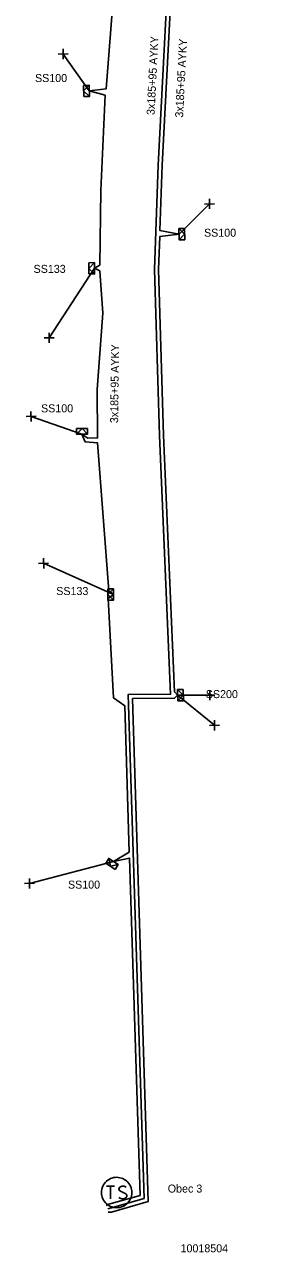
# Model space of a CAD drawing. Extents: x -762894 to -762498, y -1152897 to -1152214.
# Drawn here: x -762774.4 to -762745.3, y -1152511.5 to -1152359 of the extents above; entities that cross this region are included whole.
import ezdxf

# ---------------------------------------------------------------- set-up
doc = ezdxf.new("R2010")
doc.units = 0
for name, color, linetype in [('Vrstva 25', 7, 'Continuous'), ('Vrstva 26', 7, 'Continuous'), ('Vrstva 27', 7, 'Continuous'), ('Vrstva 31', 7, 'Continuous'), ('Vrstva 33', 7, 'Continuous'), ('Vrstva 34', 7, 'Continuous'), ('Vrstva 5', 7, 'Continuous'), ('Vrstva 59', 7, 'Continuous'), ('Vrstva 6', 7, 'Continuous')]:
    doc.layers.add(name, color=color, linetype=linetype)

msp = doc.modelspace()

# ---------------------------------------------------------------- linework, layer by layer
at = {"layer": 'Vrstva 25'}
for points in [[(-762761.027, -1152504.021), (-762761.038, -1152503.824), (-762761.069, -1152503.628), (-762761.12, -1152503.437), (-762761.192, -1152503.252), (-762761.281, -1152503.077), (-762761.389, -1152502.911), (-762761.513, -1152502.757), (-762761.653, -1152502.617), (-762761.807, -1152502.493), (-762761.973, -1152502.385), (-762762.149, -1152502.295), (-762762.333, -1152502.224), (-762762.72, -1152502.142), (-762762.72, -1152502.142), (-762762.917, -1152502.131), (-762763.115, -1152502.142), (-762763.311, -1152502.173), (-762763.501, -1152502.224), (-762763.687, -1152502.295), (-762763.862, -1152502.385), (-762764.028, -1152502.493), (-762764.182, -1152502.617), (-762764.322, -1152502.757), (-762764.446, -1152502.911), (-762764.554, -1152503.077), (-762764.644, -1152503.252), (-762764.715, -1152503.437), (-762764.766, -1152503.628), (-762764.797, -1152503.824), (-762764.808, -1152504.021), (-762764.797, -1152504.219), (-762764.766, -1152504.415), (-762764.715, -1152504.605), (-762764.644, -1152504.79), (-762764.554, -1152504.966), (-762764.446, -1152505.132), (-762764.321, -1152505.286), (-762764.182, -1152505.425), (-762764.028, -1152505.55), (-762763.862, -1152505.658), (-762763.686, -1152505.748), (-762763.501, -1152505.819), (-762763.311, -1152505.87), (-762763.115, -1152505.901), (-762762.917, -1152505.912), (-762762.72, -1152505.901), (-762762.525, -1152505.87), (-762762.333, -1152505.819), (-762762.149, -1152505.748), (-762761.973, -1152505.658), (-762761.807, -1152505.55), (-762761.653, -1152505.425), (-762761.513, -1152505.286), (-762761.389, -1152505.132), (-762761.281, -1152504.966), (-762761.192, -1152504.79), (-762761.12, -1152504.605), (-762761.069, -1152504.415), (-762761.038, -1152504.219), (-762761.027, -1152504.021)], [(-762764.179, -1152503.238), (-762763.171, -1152503.238)], [(-762763.675, -1152503.238), (-762763.675, -1152504.812)], [(-762761.722, -1152503.364), (-762761.974, -1152503.238), (-762762.289, -1152503.238), (-762762.541, -1152503.364), (-762762.667, -1152503.552), (-762762.667, -1152503.616), (-762762.541, -1152503.804), (-762761.785, -1152504.182), (-762761.659, -1152504.34), (-762761.659, -1152504.498), (-762761.785, -1152504.686), (-762762.037, -1152504.812), (-762762.289, -1152504.812), (-762762.415, -1152504.75), (-762762.667, -1152504.624)]]:
    msp.add_lwpolyline(points, dxfattribs=at)
at = {"layer": 'Vrstva 31'}
for points in [[(-762767.033, -1152366.519), (-762766.333, -1152366.507), (-762766.308, -1152367.907), (-762767.008, -1152367.919)], [(-762767.033, -1152366.519), (-762767.008, -1152367.919)], [(-762767.02, -1152367.219), (-762766.333, -1152366.507)], [(-762767.02, -1152367.219), (-762766.308, -1152367.907)], [(-762754.447, -1152385.691), (-762755.147, -1152385.703), (-762755.172, -1152384.303), (-762754.472, -1152384.291)], [(-762754.46, -1152384.991), (-762755.172, -1152384.303)], [(-762754.447, -1152385.691), (-762754.472, -1152384.291)], [(-762754.46, -1152384.991), (-762755.147, -1152385.703)], [(-762766.393, -1152388.549), (-762765.693, -1152388.537), (-762765.668, -1152389.937), (-762766.368, -1152389.949)], [(-762766.393, -1152388.549), (-762766.368, -1152389.949)], [(-762766.38, -1152389.249), (-762765.693, -1152388.537)], [(-762766.38, -1152389.249), (-762765.668, -1152389.937)], [(-762766.527, -1152409.13), (-762767.927, -1152409.13)], [(-762767.227, -1152409.13), (-762767.927, -1152409.83)], [(-762766.527, -1152409.13), (-762766.527, -1152409.83), (-762767.927, -1152409.83), (-762767.927, -1152409.13)], [(-762767.227, -1152409.13), (-762766.527, -1152409.83)], [(-762764.023, -1152429.049), (-762763.323, -1152429.037), (-762763.298, -1152430.437), (-762763.998, -1152430.449)], [(-762764.023, -1152429.049), (-762763.998, -1152430.449)], [(-762764.01, -1152429.749), (-762763.323, -1152429.037)], [(-762764.01, -1152429.749), (-762763.298, -1152430.437)], [(-762754.617, -1152442.941), (-762755.317, -1152442.953), (-762755.342, -1152441.553), (-762754.642, -1152441.541)], [(-762754.63, -1152442.241), (-762755.342, -1152441.553)], [(-762754.63, -1152442.241), (-762755.317, -1152442.953)], [(-762754.617, -1152442.941), (-762754.642, -1152441.541)], [(-762764.281, -1152463.125), (-762763.9, -1152462.538), (-762762.726, -1152463.3), (-762763.107, -1152463.887)], [(-762764.281, -1152463.125), (-762763.107, -1152463.887)], [(-762763.694, -1152463.506), (-762763.9, -1152462.538)], [(-762763.694, -1152463.506), (-762762.726, -1152463.3)]]:
    msp.add_lwpolyline(points, dxfattribs=at)
at = {"layer": 'Vrstva 34'}
for points in [[(-762770.185, -1152362.641), (-762768.935, -1152362.619)], [(-762769.549, -1152363.255), (-762769.571, -1152362.005)], [(-762752.005, -1152381.261), (-762750.755, -1152381.239)], [(-762751.369, -1152381.875), (-762751.391, -1152380.625)], [(-762771.935, -1152397.891), (-762770.685, -1152397.869)], [(-762771.299, -1152398.505), (-762771.321, -1152397.255)], [(-762773.549, -1152408.255), (-762773.571, -1152407.005)], [(-762774.185, -1152407.641), (-762772.935, -1152407.619)], [(-762771.989, -1152426.505), (-762772.011, -1152425.255)], [(-762772.625, -1152425.891), (-762771.375, -1152425.869)], [(-762751.955, -1152442.261), (-762750.705, -1152442.239)], [(-762751.319, -1152442.875), (-762751.341, -1152441.625)], [(-762751.375, -1152446.011), (-762750.125, -1152445.989)], [(-762750.739, -1152446.625), (-762750.761, -1152445.375)], [(-762773.739, -1152466.255), (-762773.761, -1152465.005)], [(-762774.375, -1152465.641), (-762773.125, -1152465.619)]]:
    msp.add_lwpolyline(points, dxfattribs=at)
at = {"layer": 'Vrstva 5'}
for points in [[(-762764.03, -1152506.05), (-762759.5, -1152504.75), (-762761.48, -1152442.16), (-762756.22, -1152442.14), (-762757.58, -1152410), (-762758.2, -1152389.39), (-762757.76, -1152376.42), (-762756.07, -1152343.75), (-762754.03, -1152318), (-762754.3, -1152317.61), (-762753.99, -1152314.18), (-762753.67, -1152314.11), (-762751.63, -1152292.79), (-762750.29, -1152273.43), (-762745.47, -1152272.59), (-762745.28, -1152272.45)], [(-762763.98, -1152506.47), (-762763.55, -1152506.48), (-762758.99, -1152505.12), (-762760.93, -1152442.68), (-762755.72, -1152442.63), (-762755.33, -1152442.25), (-762755.74, -1152441.83), (-762757.08, -1152409.98), (-762757.7, -1152389.39), (-762757.56, -1152385.31), (-762755.16, -1152385), (-762757.54, -1152384.55), (-762757.26, -1152376.45), (-762755.57, -1152343.78)], [(-762762.63, -1152346.79), (-762764.22, -1152366.95), (-762766.32, -1152367.21), (-762764.36, -1152367.75), (-762764.89, -1152379.56), (-762765.02, -1152388.85), (-762765.68, -1152389.24), (-762765.02, -1152389.56), (-762764.62, -1152394.8), (-762765.33, -1152404.3), (-762765.29, -1152410.3), (-762766.49, -1152410.34), (-762767.23, -1152409.83), (-762766.84, -1152410.79), (-762765.29, -1152410.92), (-762763.91, -1152429.31), (-762763.31, -1152429.74), (-762763.96, -1152430.24), (-762763.29, -1152442.59), (-762761.92, -1152443.57), (-762761.37, -1152461.74), (-762763.31, -1152462.92), (-762761.33, -1152462.49), (-762760.01, -1152504.38), (-762764.05, -1152505.5), (-762764.23, -1152505.64)]]:
    msp.add_lwpolyline(points, dxfattribs=at)
at = {"layer": 'Vrstva 59'}
for points in [[(-762766.32, -1152367.21), (-762769.56, -1152362.63)], [(-762755.16, -1152385), (-762751.38, -1152381.25)], [(-762765.68, -1152389.24), (-762771.31, -1152397.88)], [(-762767.23, -1152409.83), (-762773.56, -1152407.63)], [(-762763.31, -1152429.74), (-762772, -1152425.88)], [(-762755.33, -1152442.25), (-762750.75, -1152446)], [(-762755.33, -1152442.25), (-762751.33, -1152442.25)], [(-762763.31, -1152462.92), (-762773.75, -1152465.63)]]:
    msp.add_lwpolyline(points, dxfattribs=at)

# ---------------------------------------------------------------- texts
at = {"layer": 'Vrstva 26'}
msp.add_text('10018504', height=0.9943, dxfattribs=at).set_placement((-762754.97, -1152511.45))
at = {"layer": 'Vrstva 27'}
msp.add_text('Obec 3', height=0.9943, dxfattribs=at).set_placement((-762756.56, -1152504.03))
at = {"layer": 'Vrstva 33'}
for s, p in [('SS100', (-762773.07, -1152366.11)), ('SS100', (-762752.05, -1152385.32)), ('SS133', (-762773.25, -1152389.81)), ('SS100', (-762772.32, -1152407.13)), ('SS133', (-762770.43, -1152429.82)), ('SS200', (-762751.83, -1152442.62)), ('SS100', (-762768.97, -1152466.28))]:
    msp.add_text(s, height=0.9943, dxfattribs=at).set_placement(p)
at = {"layer": 'Vrstva 6'}
for height, rotation, p in [(0.99428, 87.04733, (-762758.21, -1152370.22)), (0.99428, 87.04733, (-762754.66, -1152370.55)), (0.99429, 89.17811, (-762762.74, -1152408.48))]:
    msp.add_text('3x185+95 AYKY', height=height, rotation=rotation, dxfattribs=at).set_placement(p)

doc.saveas('drawing.dxf')
